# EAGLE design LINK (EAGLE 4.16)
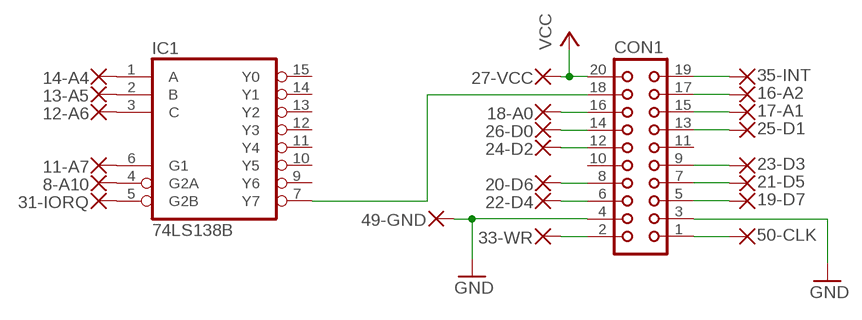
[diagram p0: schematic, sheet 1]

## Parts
8-A10  1,27-REDONDO0.8  [1,27/0,8-REDONDO]
11-A7  1,27-REDONDO0.8  [1,27/0,8-REDONDO]
12-A6  1,27-REDONDO0.8  [1,27/0,8-REDONDO]
13-A5  1,27-REDONDO0.8  [1,27/0,8-REDONDO]
14-A4  1,27-REDONDO0.8  [1,27/0,8-REDONDO]
16-A2  1,27-REDONDO0.8  [1,27/0,8-REDONDO]
17-A1  1,27-REDONDO0.8  [1,27/0,8-REDONDO]
18-A0  1,27-REDONDO0.8  [1,27/0,8-REDONDO]
19-D7  1,27-REDONDO0.8  [1,27/0,8-REDONDO]
20-D6  1,27-REDONDO0.8  [1,27/0,8-REDONDO]
21-D5  1,27-REDONDO0.8  [1,27/0,8-REDONDO]
22-D4  1,27-REDONDO0.8  [1,27/0,8-REDONDO]
23-D3  1,27-REDONDO0.8  [1,27/0,8-REDONDO]
24-D2  1,27-REDONDO0.8  [1,27/0,8-REDONDO]
25-D1  1,27-REDONDO0.8  [1,27/0,8-REDONDO]
26-D0  1,27-REDONDO0.8  [1,27/0,8-REDONDO]
27-VCC  1,27-REDONDO0.8  [1,27/0,8-REDONDO]
31-IORQ  1,27-REDONDO0.8  [1,27/0,8-REDONDO]
33-WR  1,27-REDONDO0.8  [1,27/0,8-REDONDO]
35-INT  1,27-REDONDO0.8  [1,27/0,8-REDONDO]
49-GND  1,27-REDONDO0.8  [1,27/0,8-REDONDO]
50-CLK  1,27-REDONDO0.8  [1,27/0,8-REDONDO]
CON1  4R20P  [4R20P]
IC1  74LS138B  [DIL16-B]

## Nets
CLK: 50-CLK.1(P) CON1.1
GND: 49-GND.1(P) CON1.3 CON1.4
N$8: 8-A10.1(P) IC1.4(G2A)
N$25: 33-WR.1(P) CON1.2
N$26: 19-D7.1(P) CON1.5
N$27: 22-D4.1(P) CON1.6
N$28: 21-D5.1(P) CON1.7
N$29: 20-D6.1(P) CON1.8
N$30: 23-D3.1(P) CON1.9
N$31: 24-D2.1(P) CON1.12
N$32: 26-D0.1(P) CON1.14
N$33: 25-D1.1(P) CON1.13
N$34: 17-A1.1(P) CON1.15
N$35: 16-A2.1(P) CON1.17
N$36: 35-INT.1(P) CON1.19
N$37: 14-A4.1(P) IC1.1(A)
N$38: 18-A0.1(P) CON1.16
N$39: 13-A5.1(P) IC1.2(B)
N$40: 12-A6.1(P) IC1.3(C)
N$41: 11-A7.1(P) IC1.6(G1)
N$43: 31-IORQ.1(P) IC1.5(G2B)
N$47: CON1.18 IC1.7(Y7)
VCC: 27-VCC.1(P) CON1.20
Unconnected: CON1.10 CON1.11 IC1.9(Y6) IC1.10(Y5) IC1.11(Y4) IC1.12(Y3) IC1.13(Y2) IC1.14(Y1) IC1.15(Y0)

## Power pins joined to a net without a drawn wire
GND: IC1.8(GND)
VCC: IC1.16(VCC)

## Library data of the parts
8-A10 11-A7 12-A6 13-A5 14-A4 16-A2 17-A1 18-A0 19-D7 20-D6 21-D5 22-D4 23-D3 24-D2 25-D1 26-D0 27-VCC 31-IORQ 33-WR 35-INT 49-GND 50-CLK = wirepad2:1,27-REDONDO
CON1 = con-harting:4R20P: CONNECTOR
IC1 = 74xx-eu2:74*138: 3-line to 8-line DECODER/DEMULTIPLEXER

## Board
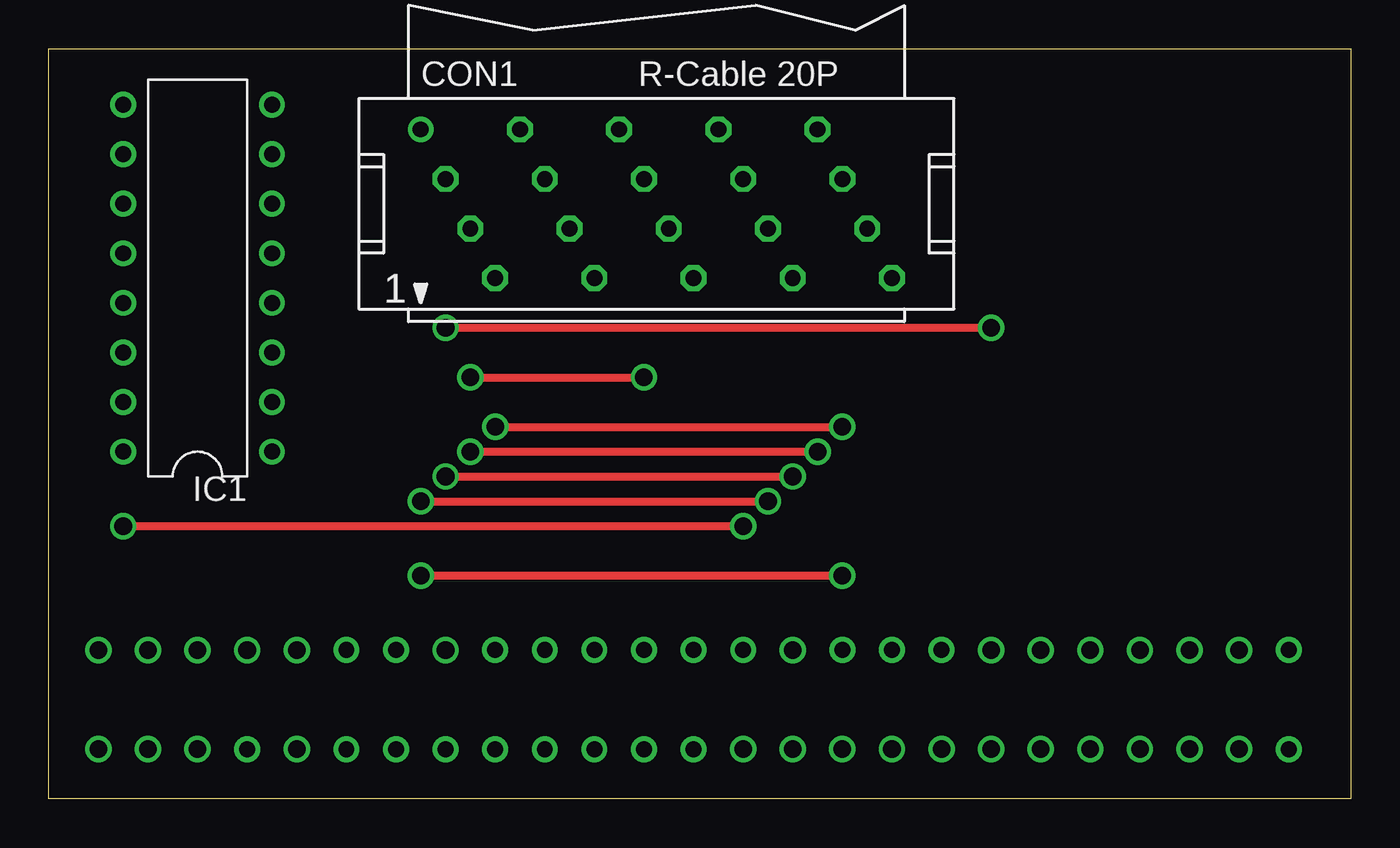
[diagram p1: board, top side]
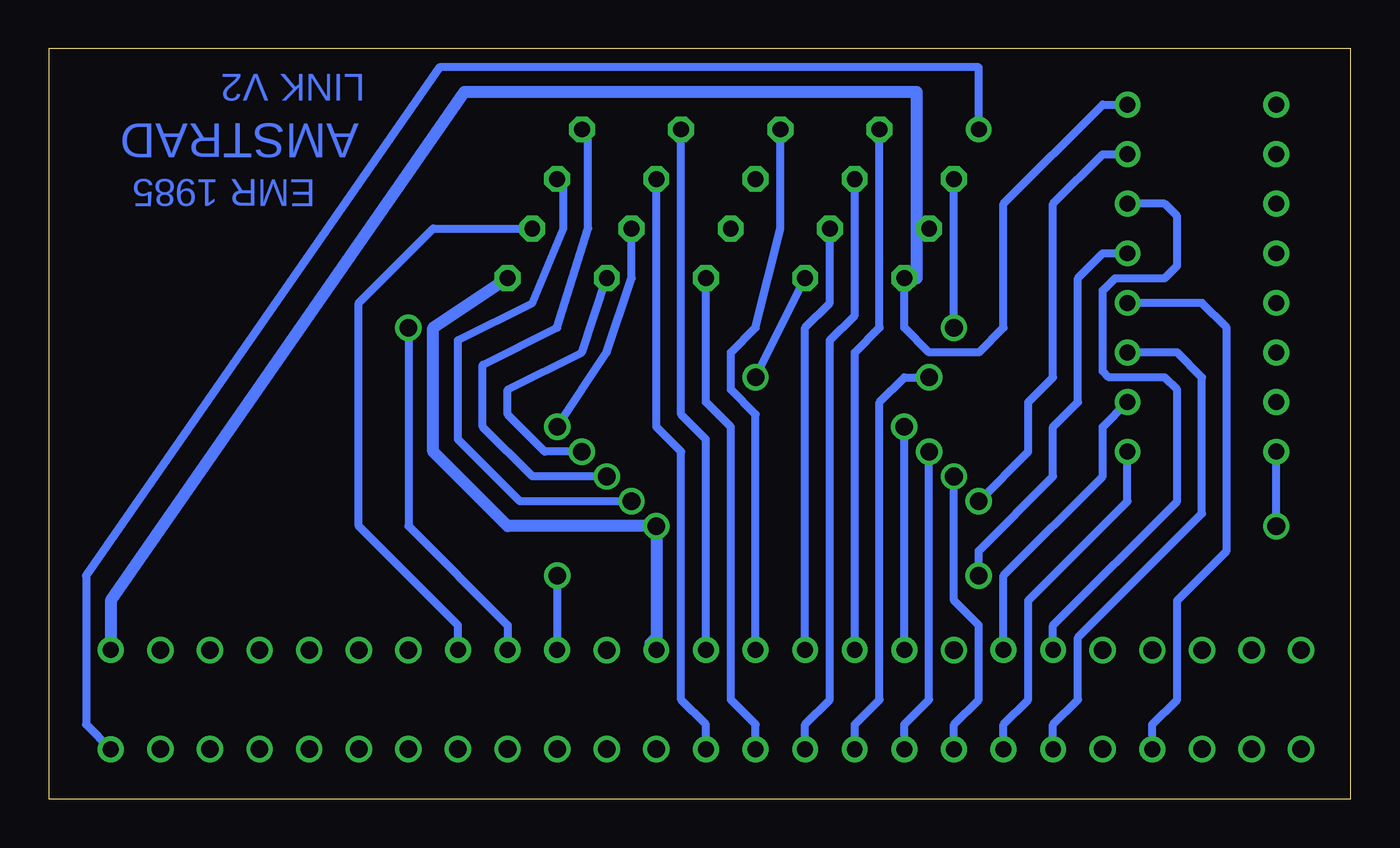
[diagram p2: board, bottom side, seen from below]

Size 66.67 x 38.42 mm. Coordinates in mm from the lower left corner, seen from the top.
Outline: 0,0 0,38.42 66.67,38.42 66.67,0 0,0
Copper layers (1*16): Top 0.035mm / dielectric 1.5mm / Bottom 0.035mm
Design rules "default": minimum track width 10mil, minimum drill 24mil, track to track 8mil, track to pad 8mil, pad to pad 8mil, via to via 8mil, smd to smd 8mil, copper to edge 40mil, drill to drill 8mil, minimum pad ring 10mil, minimum via ring 8mil, stop-mask expansion 4mil, vias tented up to drill 0mil, thermal gap 10mil

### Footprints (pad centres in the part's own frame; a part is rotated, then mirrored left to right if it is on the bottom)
1,27/0,8-REDONDO = drill 0.813 pad 1.27 round: 1 0,0
4R20P = drill 0.813 round: 1 -12.065,3.81 | drill 0.813 octagon: 2 -10.795,1.27; 3 -9.525,-1.27; 4 -8.255,-3.81; 5 -6.985,3.81; 6 -5.715,1.27; 7 -4.445,-1.27; 8 -3.175,-3.81; 9 -1.905,3.81; 10 -0.635,1.27; 11 0.635,-1.27; 12 1.905,-3.81; 13 3.175,3.81; 14 4.445,1.27; 15 5.715,-1.27; 16 6.985,-3.81; 17 8.255,3.81; 18 9.525,1.27; 19 10.795,-1.27; 20 12.065,-3.81
DIL16-B = drill 0.813 round: 1 -8.89,-3.81; 2 -6.35,-3.81; 3 -3.81,-3.81; 4 -1.27,-3.81; 5 1.27,-3.81; 6 3.81,-3.81; 7 6.35,-3.81; 8 8.89,-3.81; 9 8.89,3.81; 10 6.35,3.81; 11 3.81,3.81; 12 1.27,3.81; 13 -1.27,3.81; 14 -3.81,3.81; 15 -6.35,3.81; 16 -8.89,3.81

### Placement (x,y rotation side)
8-A10  10.16,2.54 180 top
11-A7  15.24,7.62 0 top
12-A6  15.24,2.54 180 top
13-A5  17.78,7.62 0 top
14-A4  17.78,2.54 180 top
16-A2  20.32,2.54 180 top
17-A1  22.86,7.62 0 top
18-A0  22.86,2.54 180 top
19-D7  25.4,7.62 0 top
20-D6  25.4,2.54 180 top
21-D5  27.94,7.62 0 top
22-D4  27.94,2.54 180 top
23-D3  30.48,7.62 0 top
24-D2  30.48,2.54 180 top
25-D1  33.02,7.62 0 top
26-D0  33.02,2.54 180 top
27-VCC  35.56,7.62 0 top
31-IORQ  40.64,7.62 0 top
33-WR  43.18,7.62 0 top
35-INT  45.72,7.62 0 top
49-GND  63.5,7.62 0 top
50-CLK  63.5,2.54 180 top
CON1  31.11,30.48 0 top
IC1  7.62,26.67 90 top

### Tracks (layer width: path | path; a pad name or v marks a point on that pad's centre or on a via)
CLK
  Bottom 0.406: 50-CLK.1 64.77,3.81 64.77,11.43 46.67,37.47 19.05,37.47 CON1.1
GND
  Bottom 0.406: IC1.8 12.7,35.56 17.78,30.48 17.78,24.13 19.05,22.86 21.59,22.86 22.86,24.13 CON1.4
  Bottom 0.61: 49-GND.1 63.5,10.16 45.4,36.2 22.23,36.2 22.23,29.21 | 22.23,29.21 CON1.3 | CON1.4 22.23,26.67 22.23,29.21
N$2  (via drill 0.9)
  other vias: 2.54,7.62
N$4  (via drill 0.9)
  other vias: 43.18,2.54
N$5  (via drill 0.9)
  other vias: 55.88,7.62
N$8
  Bottom 0.406: IC1.4 7.62,25.4 6.35,24.13 6.35,12.7 8.89,10.16 8.89,5.08 10.16,3.81 8-A10.1 10.16,2.22
N$9  (via drill 0.9)
  other vias: 48.26,2.54
N$10  (via drill 0.9)
  other vias: 48.26,7.62
N$11  (via drill 0.9)
  other vias: 50.8,7.62
N$12  (via drill 0.9)
  other vias: 53.34,2.54
N$13  (via drill 0.9)
  other vias: 55.88,2.54
N$14  (via drill 0.9)
  other vias: 58.42,2.54
N$22  (via drill 0.9)
  other vias: 60.96,2.54
N$23  (via drill 0.9)
  other vias: 60.96,7.62
N$24  (via drill 0.9)
  other vias: 2.54,2.54
N$25  (via drill 0.9)
  Top 0.406: v20.32,24.13 v48.26,24.13
  Bottom 0.406: v20.32,24.13 CON1.2 | v48.26,24.13 48.26,13.97 43.18,8.89 33-WR.1
N$26
  Bottom 0.406: 19-D7.1 25.4,22.86 24.13,24.13 CON1.5
N$27
  Bottom 0.406: CON1.6 25.4,24.77 26.67,23.5 26.67,5.08 27.94,3.81 27.94,2.86 28.26,2.54 22-D4.1
N$28
  Bottom 0.406: CON1.7 26.67,25.4 27.94,24.13 21-D5.1
N$29  (via drill 0.9)
  Top 0.406: v21.59,21.59 v30.48,21.59
  Bottom 0.406: v30.48,21.59 CON1.8 | v21.59,21.59 22.86,21.59 24.13,20.32 24.13,5.08 25.4,3.81 20-D6.1 25.4,2.22
N$30
  Bottom 0.406: CON1.9 29.21,29.21 30.48,24.13 31.75,22.86 31.75,20.95 30.48,19.68 23-D3.1
N$31
  Bottom 0.406: CON1.12 33.02,20.32 31.75,19.05 31.75,5.08 30.48,3.81 24-D2.1 30.48,2.22
N$32
  Bottom 0.406: CON1.14 35.56,19.05 34.29,17.78 34.29,5.08 33.02,3.81 26-D0.1 33.02,2.22
N$33
  Bottom 0.406: CON1.13 34.29,19.68 33.02,18.41 25-D1.1
N$34  (via drill 0.9)
  Top 0.406: v22.86,19.05 v40.64,19.05
  Bottom 0.406: 17-A1.1 v22.86,19.05 | v40.64,19.05 38.1,22.86 36.83,26.67 CON1.15
N$35  (via drill 0.9)
  Top 0.406: v20.32,16.51 v38.1,16.51
  Bottom 0.406: 16-A2.1 20.32,3.81 19.05,5.08 19.05,8.89 20.32,10.16 v20.32,16.51 | v38.1,16.51 41.91,16.51 44.45,19.05 44.45,22.23 40.64,24.13 39.05,29.21 39.05,33.97 CON1.17
N$36
  Bottom 0.406: 35-INT.1 45.72,8.89 50.8,13.97 50.8,25.4 46.99,29.21 CON1.19
N$37
  Bottom 0.406: IC1.1 11.43,15.24 16.51,10.16 16.51,5.08 17.78,3.81 14-A4.1 17.78,2.22
N$38  (via drill 0.9)
  Top 0.406: v21.59,17.78 v39.37,17.78
  Bottom 0.406: 18-A0.1 22.86,3.81 21.59,5.08 v21.59,17.78 | v39.37,17.78 41.27,17.78 43.18,19.68 43.18,20.95 39.37,22.86 CON1.16
N$39
  Bottom 0.406: 13-A5.1 17.78,11.43 12.7,16.51 12.7,19.05 IC1.2
N$40
  Bottom 0.406: 12-A6.1 15.24,3.81 13.97,5.08 13.97,8.26 7.62,14.61 7.62,21.59 8.89,22.86 IC1.3
N$41
  Bottom 0.406: 11-A7.1 15.24,8.89 8.89,15.24 8.89,20.95 9.53,21.59 12.38,21.59 12.7,21.91 12.7,26.04 12.06,26.67 9.53,26.67 8.89,27.3 8.89,29.84 9.53,30.48 IC1.6
N$42  (via drill 0.9)
  other vias: 50.8,2.54
N$43  (via drill 0.9)
  Top 0.406: v19.05,11.43 v40.64,11.43
  Bottom 0.406: IC1.5 12.7,27.94 13.97,26.67 13.97,20.32 15.24,19.05 15.24,16.51 19.05,12.7 v19.05,11.43 | v40.64,11.43 31-IORQ.1
N$44  (via drill 0.9)
  other vias: 45.72,2.54
N$45  (via drill 0.9)
  other vias: 58.42,7.62
N$46  (via drill 0.9)
  other vias: 53.34,7.62
N$47  (via drill 0.9)
  Top 0.406: v19.05,15.24 v36.83,15.24
  Bottom 0.406: IC1.7 12.7,33.02 15.24,30.48 15.24,21.59 16.51,20.32 16.51,17.78 v19.05,15.24 | v36.83,15.24 42.55,15.24 45.72,18.41 45.72,23.5 41.91,25.4 40.32,29.21 40.32,31.43 CON1.18
N$48  (via drill 0.9)
  other vias: 5.08,2.54
N$49  (via drill 0.9)
  other vias: 7.62,2.54
N$50  (via drill 0.9)
  other vias: 38.1,7.62
N$51  (via drill 0.9)
  other vias: 38.1,2.54
N$52  (via drill 0.9)
  other vias: 40.64,2.54
N$53  (via drill 0.9)
  other vias: 35.56,2.54
N$54  (via drill 0.9)
  other vias: 7.62,7.62
N$55  (via drill 0.9)
  other vias: 5.08,7.62
N$56  (via drill 0.9)
  other vias: 10.16,7.62
N$57  (via drill 0.9)
  other vias: 20.32,7.62
N$58  (via drill 0.9)
  other vias: 12.7,2.54
N$61  (via drill 0.9)
  other vias: 12.7,7.62
VCC  (via drill 0.9)
  Top 0.406: v3.81,13.97 v35.56,13.97
  Bottom 0.406: v3.81,13.97 IC1.16
  Bottom 0.61: 27-VCC.1 35.88,7.94 35.56,8.26 v35.56,13.97 43.18,13.97 46.99,17.78 46.99,24.13 CON1.20

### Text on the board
Bottom: LINK V2 | AMSTRAD | EMR 1985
